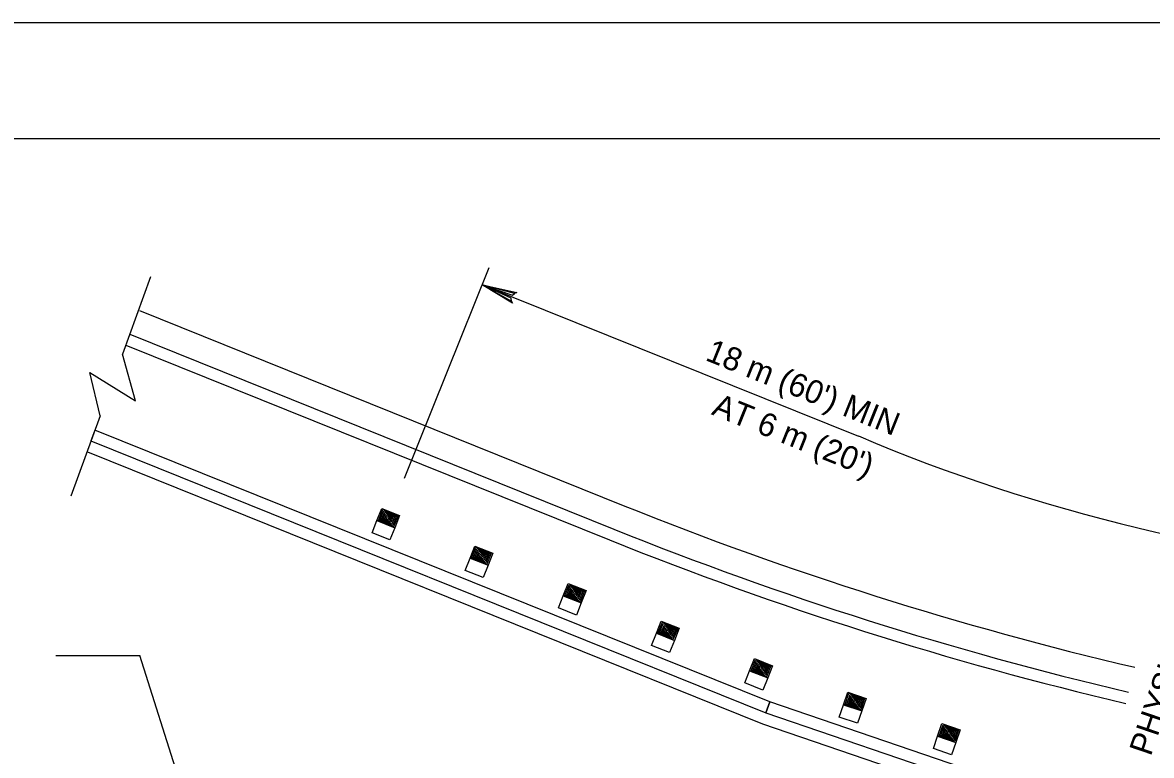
# Model space of a CAD drawing. Extents: x 639362 to 641108, y 298458 to 299646.
# Drawn here: x 639506.2 to 639652.3, y 299550.9 to 299645.6 of the extents above; entities that cross this region are included whole.
import ezdxf

# ---------------------------------------------------------------- set-up
doc = ezdxf.new("R2010")
doc.units = 0
for name, color, linetype in [('1', 7, 'Continuous'), ('2', 7, 'Continuous'), ('PLT-BNDY', 7, 'Continuous')]:
    doc.layers.add(name, color=color, linetype=linetype)

msp = doc.modelspace()

# ---------------------------------------------------------------- linework, layer by layer
at = {"layer": '1'}
msp.add_line((639402.31, 299630.63), (640188.31, 299630.63), dxfattribs=at)
at = {"layer": '2'}
for p, q in [((639566.54, 299613.91), (639555.59, 299586.69)), ((639522.78, 299612.73), (639519.14, 299602.75)), ((639565.67, 299611.73), (639614.34, 299592.15)), ((639521.32, 299608.4), (639583.93, 299583.19)), ((639520.09, 299605.34), (639582.7, 299580.13)), ((639519.57, 299603.93), (639582.14, 299578.74)), ((639520.82, 299596.71), (639519.14, 299602.75)), ((639516.24, 299594.78), (639514.89, 299600.36)), ((639514.89, 299600.36), (639520.82, 299596.71)), ((639516.24, 299594.78), (639512.45, 299584.37)), ((639515.57, 299592.94), (639515.06, 299591.53)), ((639602.91, 299557.79), (639515.57, 299592.94)), ((639515.06, 299591.53), (639602.39, 299556.38)), ((639614.34, 299592.15), (639614.34, 299592.16)), ((639514.6, 299590.1), (639601.94, 299554.95)), ((639552.04, 299581.22), (639552.67, 299582.8)), ((639552.67, 299582.8), (639554.99, 299581.88)), ((639554.37, 299580.3), (639552.04, 299581.22)), ((639552.24, 299581.23), (639552.81, 299582.65)), ((639554.22, 299580.44), (639552.24, 299581.23)), ((639552.45, 299581.27), (639552.93, 299582.48)), ((639554.1, 299580.61), (639552.45, 299581.27)), ((639552.66, 299581.31), (639553.06, 299582.31)), ((639553.98, 299580.78), (639552.66, 299581.31)), ((639552.81, 299582.65), (639554.79, 299581.87)), ((639552.87, 299581.35), (639553.18, 299582.14)), ((639553.86, 299580.96), (639552.87, 299581.35)), ((639552.93, 299582.48), (639554.58, 299581.83)), ((639553.06, 299582.31), (639554.38, 299581.79)), ((639553.07, 299581.39), (639553.3, 299581.97)), ((639553.73, 299581.13), (639553.07, 299581.39)), ((639553.18, 299582.14), (639554.17, 299581.75)), ((639553.28, 299581.43), (639553.43, 299581.8)), ((639553.61, 299581.3), (639553.28, 299581.43)), ((639553.3, 299581.97), (639553.96, 299581.71)), ((639553.43, 299581.8), (639553.76, 299581.67)), ((639553.55, 299581.63), (639553.49, 299581.47)), ((639553.76, 299581.67), (639553.61, 299581.3)), ((639553.96, 299581.71), (639553.73, 299581.13)), ((639554.17, 299581.75), (639553.86, 299580.96)), ((639554.38, 299581.79), (639553.98, 299580.78)), ((639554.58, 299581.83), (639554.1, 299580.61)), ((639554.79, 299581.87), (639554.22, 299580.44)), ((639554.99, 299581.88), (639554.37, 299580.3)), ((639564.1, 299576.37), (639564.73, 299577.94)), ((639564.3, 299576.37), (639564.87, 299577.8)), ((639564.51, 299576.41), (639564.99, 299577.63)), ((639564.72, 299576.45), (639565.12, 299577.45)), ((639564.73, 299577.94), (639567.05, 299577.02)), ((639564.87, 299577.8), (639566.85, 299577.01)), ((639564.93, 299576.49), (639565.24, 299577.28)), ((639564.99, 299577.63), (639566.64, 299576.97)), ((639565.12, 299577.45), (639566.44, 299576.93)), ((639565.13, 299576.53), (639565.36, 299577.11)), ((639565.24, 299577.28), (639566.23, 299576.89)), ((639565.34, 299576.57), (639565.49, 299576.94)), ((639565.36, 299577.11), (639566.02, 299576.85)), ((639565.49, 299576.94), (639565.82, 299576.81)), ((639566.02, 299576.85), (639565.79, 299576.27)), ((639566.23, 299576.89), (639565.92, 299576.1)), ((639566.44, 299576.93), (639566.04, 299575.93)), ((639566.64, 299576.97), (639566.16, 299575.76)), ((639566.85, 299577.01), (639566.28, 299575.59)), ((639567.05, 299577.02), (639566.43, 299575.45)), ((639566.43, 299575.45), (639564.1, 299576.37)), ((639566.28, 299575.59), (639564.3, 299576.37)), ((639566.16, 299575.76), (639564.51, 299576.41)), ((639566.04, 299575.93), (639564.72, 299576.45)), ((639565.92, 299576.1), (639564.93, 299576.49)), ((639565.79, 299576.27), (639565.13, 299576.53)), ((639565.67, 299576.44), (639565.34, 299576.57)), ((639565.61, 299576.77), (639565.55, 299576.61)), ((639565.82, 299576.81), (639565.67, 299576.44)), ((639576.16, 299571.51), (639576.79, 299573.09)), ((639576.36, 299571.52), (639576.93, 299572.94)), ((639576.57, 299571.56), (639577.05, 299572.77)), ((639576.78, 299571.6), (639577.18, 299572.6)), ((639576.79, 299573.09), (639579.11, 299572.17)), ((639576.93, 299572.94), (639578.91, 299572.16)), ((639577.05, 299572.77), (639578.7, 299572.12)), ((639577.18, 299572.6), (639578.5, 299572.08)), ((639578.49, 299570.59), (639576.16, 299571.51)), ((639578.34, 299570.74), (639576.36, 299571.52)), ((639578.22, 299570.91), (639576.57, 299571.56)), ((639578.1, 299571.08), (639576.78, 299571.6)), ((639576.99, 299571.64), (639577.3, 299572.43)), ((639577.98, 299571.25), (639576.99, 299571.64)), ((639577.19, 299571.68), (639577.42, 299572.26)), ((639577.85, 299571.42), (639577.19, 299571.68)), ((639577.3, 299572.43), (639578.29, 299572.04)), ((639577.4, 299571.72), (639577.55, 299572.09)), ((639577.73, 299571.59), (639577.4, 299571.72)), ((639577.42, 299572.26), (639578.08, 299572)), ((639577.55, 299572.09), (639577.88, 299571.96)), ((639577.67, 299571.92), (639577.6, 299571.76)), ((639577.88, 299571.96), (639577.73, 299571.59)), ((639578.08, 299572), (639577.85, 299571.42)), ((639578.29, 299572.04), (639577.98, 299571.25)), ((639578.5, 299572.08), (639578.1, 299571.08)), ((639578.7, 299572.12), (639578.22, 299570.91)), ((639578.91, 299572.16), (639578.34, 299570.74)), ((639579.11, 299572.17), (639578.49, 299570.59)), ((639588.22, 299566.66), (639588.85, 299568.24)), ((639588.42, 299566.66), (639588.99, 299568.09)), ((639588.85, 299568.24), (639591.17, 299567.32)), ((639588.99, 299568.09), (639590.97, 299567.31)), ((639590.55, 299565.74), (639588.22, 299566.66)), ((639590.4, 299565.88), (639588.42, 299566.66)), ((639588.63, 299566.7), (639589.11, 299567.92)), ((639590.28, 299566.05), (639588.63, 299566.7)), ((639588.84, 299566.74), (639589.24, 299567.75)), ((639590.16, 299566.22), (639588.84, 299566.74)), ((639589.05, 299566.78), (639589.36, 299567.58)), ((639590.04, 299566.39), (639589.05, 299566.78)), ((639589.11, 299567.92), (639590.76, 299567.26)), ((639589.24, 299567.75), (639590.56, 299567.22)), ((639589.25, 299566.83), (639589.48, 299567.41)), ((639589.91, 299566.56), (639589.25, 299566.83)), ((639589.36, 299567.58), (639590.35, 299567.18)), ((639589.46, 299566.86), (639589.61, 299567.23)), ((639589.79, 299566.73), (639589.46, 299566.86)), ((639589.48, 299567.41), (639590.14, 299567.14)), ((639589.61, 299567.23), (639589.94, 299567.1)), ((639589.73, 299567.07), (639589.66, 299566.91)), ((639589.94, 299567.1), (639589.79, 299566.73)), ((639590.14, 299567.14), (639589.91, 299566.56)), ((639590.35, 299567.18), (639590.04, 299566.39)), ((639590.56, 299567.22), (639590.16, 299566.22)), ((639590.76, 299567.26), (639590.28, 299566.05)), ((639590.97, 299567.31), (639590.4, 299565.88)), ((639591.17, 299567.32), (639590.55, 299565.74)), ((639510.49, 299563.76), (639521.36, 299563.76)), ((639530.34, 299535.6), (639521.36, 299563.76)), ((639600.28, 299561.8), (639600.91, 299563.38)), ((639600.48, 299561.81), (639601.05, 299563.23)), ((639600.69, 299561.85), (639601.17, 299563.06)), ((639600.9, 299561.89), (639601.3, 299562.89)), ((639600.91, 299563.38), (639603.23, 299562.46)), ((639601.05, 299563.23), (639603.03, 299562.45)), ((639601.11, 299561.93), (639601.42, 299562.72)), ((639601.17, 299563.06), (639602.82, 299562.41)), ((639601.3, 299562.89), (639602.62, 299562.37)), ((639601.31, 299561.97), (639601.54, 299562.55)), ((639601.42, 299562.72), (639602.41, 299562.33)), ((639601.52, 299562.01), (639601.67, 299562.38)), ((639601.54, 299562.55), (639602.2, 299562.29)), ((639601.67, 299562.38), (639602, 299562.25)), ((639602, 299562.25), (639601.85, 299561.88)), ((639602.2, 299562.29), (639601.97, 299561.71)), ((639602.41, 299562.33), (639602.1, 299561.54)), ((639602.62, 299562.37), (639602.22, 299561.37)), ((639602.82, 299562.41), (639602.34, 299561.2)), ((639603.03, 299562.45), (639602.46, 299561.03)), ((639603.23, 299562.46), (639602.61, 299560.88)), ((639602.61, 299560.88), (639600.28, 299561.8)), ((639602.46, 299561.03), (639600.48, 299561.81)), ((639602.34, 299561.2), (639600.69, 299561.85)), ((639602.22, 299561.37), (639600.9, 299561.89)), ((639602.1, 299561.54), (639601.11, 299561.93)), ((639601.97, 299561.71), (639601.31, 299561.97)), ((639601.85, 299561.88), (639601.52, 299562.01)), ((639601.79, 299562.21), (639601.72, 299562.05)), ((639612.44, 299557.42), (639612.99, 299559.03)), ((639612.64, 299557.44), (639613.13, 299558.89)), ((639612.84, 299557.49), (639613.27, 299558.72)), ((639612.99, 299559.03), (639615.35, 299558.22)), ((639613.05, 299557.54), (639613.4, 299558.56)), ((639613.13, 299558.89), (639615.15, 299558.2)), ((639613.25, 299557.59), (639613.53, 299558.39)), ((639613.27, 299558.72), (639614.95, 299558.15)), ((639613.4, 299558.56), (639614.74, 299558.1)), ((639613.46, 299557.64), (639613.66, 299558.23)), ((639613.53, 299558.39), (639614.54, 299558.05)), ((639613.66, 299558.23), (639614.33, 299558)), ((639613.66, 299557.69), (639613.79, 299558.06)), ((639613.79, 299558.06), (639614.13, 299557.95)), ((639613.92, 299557.9), (639613.86, 299557.74)), ((639614.13, 299557.95), (639614, 299557.57)), ((639614.33, 299558), (639614.13, 299557.41)), ((639614.54, 299558.05), (639614.26, 299557.24)), ((639614.74, 299558.1), (639614.39, 299557.08)), ((639614.95, 299558.15), (639614.52, 299556.91)), ((639615.15, 299558.2), (639614.65, 299556.75)), ((639615.35, 299558.22), (639614.8, 299556.61)), ((639602.91, 299557.79), (639602.39, 299556.38)), ((639602.39, 299556.38), (639602.91, 299557.79)), ((639650.51, 299541.55), (639602.91, 299557.79)), ((639614.8, 299556.61), (639612.44, 299557.42)), ((639614.65, 299556.75), (639612.64, 299557.44)), ((639614.52, 299556.91), (639612.84, 299557.49)), ((639614.39, 299557.08), (639613.05, 299557.54)), ((639614.26, 299557.24), (639613.25, 299557.59)), ((639614.13, 299557.41), (639613.46, 299557.64)), ((639614, 299557.57), (639613.66, 299557.69)), ((639601.94, 299554.95), (639645.41, 299540.11)), ((639602.39, 299556.38), (639650.01, 299540.13)), ((639624.6, 299553.37), (639625.16, 299554.97)), ((639625.16, 299554.97), (639627.52, 299554.15)), ((639624.81, 299553.39), (639625.31, 299554.83)), ((639625.01, 299553.43), (639625.44, 299554.67)), ((639625.22, 299553.48), (639625.57, 299554.5)), ((639626.56, 299553.02), (639625.22, 299553.48)), ((639625.31, 299554.83), (639627.32, 299554.14)), ((639625.42, 299553.53), (639625.7, 299554.34)), ((639626.43, 299553.18), (639625.42, 299553.53)), ((639625.44, 299554.67), (639627.12, 299554.09)), ((639625.57, 299554.5), (639626.91, 299554.04)), ((639625.63, 299553.58), (639625.83, 299554.17)), ((639626.3, 299553.35), (639625.63, 299553.58)), ((639625.7, 299554.34), (639626.71, 299553.99)), ((639625.83, 299554.17), (639626.5, 299553.94)), ((639625.83, 299553.63), (639625.96, 299554.01)), ((639626.17, 299553.51), (639625.83, 299553.63)), ((639625.96, 299554.01), (639626.3, 299553.89)), ((639626.09, 299553.84), (639626.03, 299553.68)), ((639626.3, 299553.89), (639626.17, 299553.51)), ((639626.5, 299553.94), (639626.3, 299553.35)), ((639626.71, 299553.99), (639626.43, 299553.18)), ((639626.91, 299554.04), (639626.56, 299553.02)), ((639627.12, 299554.09), (639626.69, 299552.85)), ((639627.32, 299554.14), (639626.82, 299552.69)), ((639627.52, 299554.15), (639626.97, 299552.55)), ((639626.97, 299552.55), (639624.6, 299553.37)), ((639626.82, 299552.69), (639624.81, 299553.39)), ((639626.69, 299552.85), (639625.01, 299553.43))]:
    msp.add_line(p, q, dxfattribs=at)
msp.add_lwpolyline([(639569.47, 299609.62), (639569.43, 299609.97), (639565.67, 299611.73), (639569.47, 299609.62), (639569.6, 299609.36), (639565.67, 299611.73), (639569.6, 299610.37), (639569.85, 299610.6), (639565.67, 299611.73), (639570.15, 299610.71), (639569.85, 299610.6)], dxfattribs=at)
for points in [[(639552.04, 299581.22), (639554.37, 299580.3), (639553.74, 299578.72), (639551.42, 299579.64)], [(639564.1, 299576.37), (639566.43, 299575.45), (639565.8, 299573.87), (639563.48, 299574.79)], [(639576.16, 299571.51), (639578.49, 299570.59), (639577.86, 299569.01), (639575.54, 299569.93)], [(639588.22, 299566.66), (639590.55, 299565.74), (639589.92, 299564.16), (639587.6, 299565.08)], [(639600.28, 299561.8), (639602.61, 299560.88), (639601.98, 299559.31), (639599.66, 299560.23)], [(639612.44, 299557.42), (639614.8, 299556.61), (639614.25, 299555.01), (639611.88, 299555.82)], [(639624.6, 299553.37), (639626.97, 299552.55), (639626.41, 299550.95), (639624.05, 299551.77)]]:
    msp.add_lwpolyline(points, close=True, dxfattribs=at)
for centre, radius, start, end in [((639703.35, 299802.11), 228.03, 247.0247, 266.1831), ((639754.09, 300005.93), 455.7, 248.0743, 256.8081), ((639754.09, 300005.93), 459, 248.0743, 256.8042), ((639754.09, 300005.93), 460.5, 248.0743, 256.8042)]:
    msp.add_arc(centre, radius, start, end, dxfattribs=at)
at = {"layer": 'PLT-BNDY'}
msp.add_lwpolyline([(639362.31, 299645.63), (640203.31, 299645.63), (640203.31, 299051.63), (639362.31, 299051.63)], close=True, dxfattribs=at)

# ---------------------------------------------------------------- texts
at = {"layer": '2'}
for s, rotation, p in [("18 m (60') MIN", 338.0767, (639594.42, 299602.01)), ("AT 6 m (20')", 338.0767, (639595.22, 299594.99)), ('PHYSICAL', 71.1572, (639652.17, 299550.66))]:
    msp.add_text(s, height=3, rotation=rotation, dxfattribs=at).set_placement(p)

doc.saveas('drawing.dxf')
